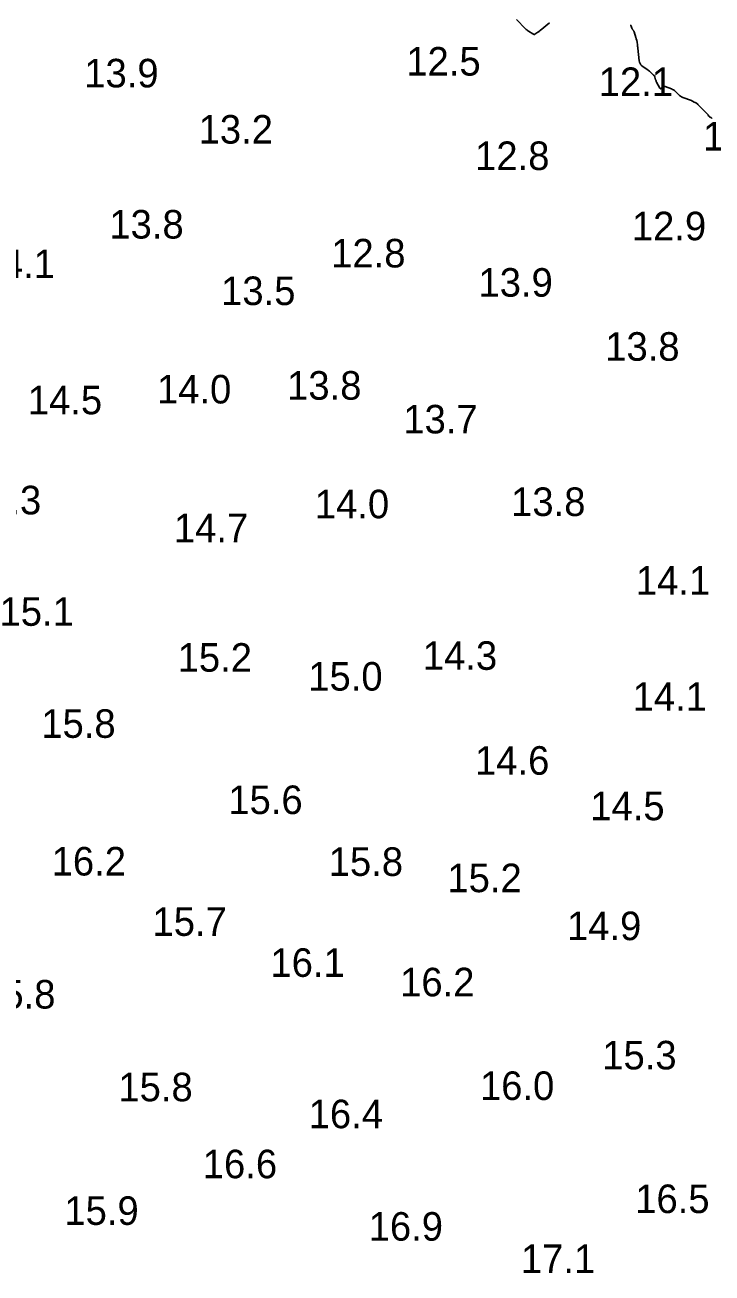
# Model space of a CAD drawing. Extents: x 815352 to 820877, y 582403 to 597439.
# Drawn here: x 819682.5 to 819802.8, y 593298.9 to 593517.5 of the extents above; entities that cross this region are included whole.
import ezdxf

# ---------------------------------------------------------------- set-up
doc = ezdxf.new("R2010")
doc.units = 0
doc.layers.add('V-CONT-EL12', color=7, linetype='Continuous')
doc.layers.add('V-TOPO-SOUN', color=7, linetype='Continuous')

msp = doc.modelspace()

# ---------------------------------------------------------------- linework, layer by layer
at = {"layer": 'V-CONT-EL12'}
for points in [[(819774.3, 593517.83), (819772.68, 593516.5), (819772.58, 593516.43), (819772.49, 593516.36), (819772.4, 593516.29), (819772.3, 593516.22), (819771.78, 593515.84), (819771.75, 593515.83), (819771.71, 593515.82), (819771.68, 593515.82), (819771.65, 593515.83), (819771.51, 593515.88), (819771.48, 593515.9), (819771.44, 593515.91), (819771.41, 593515.93), (819771.38, 593515.95), (819770.62, 593516.41), (819770.48, 593516.5), (819770.35, 593516.6), (819770.23, 593516.7), (819770.12, 593516.81), (819768.55, 593518.44)], [(819802.77, 593501.12), (819802.72, 593501.15), (819802.67, 593501.19), (819802.62, 593501.22), (819802.57, 593501.25), (819802.34, 593501.39), (819802.3, 593501.42), (819802.27, 593501.45), (819802.23, 593501.49), (819802.2, 593501.53), (819802.1, 593501.7), (819802.07, 593501.74), (819802.04, 593501.78), (819802.01, 593501.82), (819801.97, 593501.86), (819800.3, 593503.56), (819800.22, 593503.64), (819800.13, 593503.71), (819800.04, 593503.77), (819799.95, 593503.83), (819799.55, 593504.04), (819799.45, 593504.09), (819799.35, 593504.14), (819799.25, 593504.19), (819799.15, 593504.23), (819797.64, 593504.8), (819797.45, 593504.89), (819797.27, 593504.99), (819797.1, 593505.11), (819796.95, 593505.25), (819796.36, 593505.84), (819796.21, 593505.98), (819796.04, 593506.1), (819795.86, 593506.2), (819795.67, 593506.29), (819794.58, 593506.68), (819794.49, 593506.71), (819794.39, 593506.7), (819794.3, 593506.68), (819794.22, 593506.62), (819793.89, 593506.36), (819793.81, 593506.32), (819793.74, 593506.31), (819793.68, 593506.35), (819793.63, 593506.42), (819793.06, 593507.47), (819793.01, 593507.57), (819792.96, 593507.67), (819792.92, 593507.78), (819792.89, 593507.88), (819792.77, 593508.32), (819792.73, 593508.43), (819792.68, 593508.52), (819792.62, 593508.61), (819792.54, 593508.69), (819792.04, 593509.16), (819791.92, 593509.26), (819791.81, 593509.36), (819791.69, 593509.46), (819791.57, 593509.55), (819790.5, 593510.33), (819790.31, 593510.51), (819790.16, 593510.71), (819790.06, 593510.94), (819790, 593511.19), (819789.76, 593513.44), (819789.75, 593513.56), (819789.73, 593513.68), (819789.72, 593513.8), (819789.71, 593513.93), (819789.65, 593514.52), (819789.64, 593514.59), (819789.63, 593514.65), (819789.61, 593514.72), (819789.59, 593514.78), (819789.51, 593515.04), (819789.49, 593515.1), (819789.47, 593515.17), (819789.45, 593515.23), (819789.43, 593515.29), (819789.12, 593516.3), (819789.1, 593516.36), (819789.07, 593516.41), (819789.04, 593516.46), (819789.01, 593516.52), (819788.86, 593516.71), (819788.82, 593516.76), (819788.79, 593516.81), (819788.76, 593516.87), (819788.74, 593516.92), (819788.6, 593517.28), (819788.57, 593517.36), (819788.54, 593517.44), (819788.5, 593517.51)]]:
    msp.add_lwpolyline(points, dxfattribs=at)

# ---------------------------------------------------------------- texts
at = {"layer": 'V-TOPO-SOUN'}
for s, p in [('12.5 ', (819749.26, 593508.61)), ('13.9 ', (819692.9, 593506.54)), ('12.1 ', (819782.93, 593505.03)), ('13.2 ', (819712.91, 593496.7)), ('11.3 ', (819801.2, 593495.49)), ('12.8 ', (819761.3, 593492.07)), ('13.8 ', (819697.29, 593480.07)), ('12.9 ', (819788.73, 593479.77)), ('12.8 ', (819736.11, 593475.01)), ('14.1 ', (819674.76, 593473.14)), ('13.5 ', (819716.85, 593468.42)), ('13.9 ', (819761.89, 593469.89)), ('13.8 ', (819784.07, 593458.67)), ('14.0 ', (819705.62, 593451.19)), ('13.8 ', (819728.4, 593451.85)), ('14.5 ', (819683.02, 593449.29)), ('13.7 ', (819748.74, 593445.94)), ('15.3 ', (819672.36, 593431.77)), ('14.0 ', (819733.25, 593431.08)), ('13.8 ', (819767.6, 593431.48)), ('14.7 ', (819708.58, 593426.88)), ('14.1 ', (819789.43, 593417.7)), ('15.1 ', (819678.07, 593412.25)), ('15.2 ', (819709.24, 593404.21)), ('14.3 ', (819752.15, 593404.54)), ('15.0 ', (819732.1, 593400.9)), ('14.1 ', (819788.87, 593397.36)), ('15.8 ', (819685.38, 593392.63)), ('14.6 ', (819761.28, 593386.17)), ('15.6 ', (819718.11, 593379.28)), ('14.5 ', (819781.45, 593378.2)), ('16.2 ', (819687.19, 593368.52)), ('15.8 ', (819735.68, 593368.45)), ('15.2 ', (819756.45, 593365.6)), ('15.7 ', (819704.84, 593357.95)), ('14.9 ', (819777.38, 593357.2)), ('16.1 ', (819725.48, 593350.77)), ('16.2 ', (819748.18, 593347.36)), ('15.8 ', (819674.85, 593345.22)), ('15.3 ', (819783.55, 593334.56)), ('15.8 ', (819698.87, 593328.98)), ('16.0 ', (819762.15, 593329.21)), ('16.4 ', (819732.17, 593324.26)), ('16.6 ', (819713.64, 593315.5)), ('16.5 ', (819789.32, 593309.4)), ('15.9 ', (819689.42, 593307.33)), ('16.9 ', (819742.67, 593304.57)), ('17.1 ', (819769.31, 593298.9))]:
    msp.add_text(s, height=5, dxfattribs=at).set_placement(p)

doc.saveas('drawing.dxf')
